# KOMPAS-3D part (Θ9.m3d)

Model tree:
1. Эскиз:1
2. Операция выдавливания:1
     Расстояние 1 = 2
3. Скругление:1
     Радиус = 2
4. Эскиз:2
5. Вырезать элемент выдавливания:1
     Расстояние 1 = 10
6. Скругление:2
     Радиус = 2
